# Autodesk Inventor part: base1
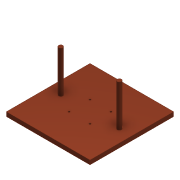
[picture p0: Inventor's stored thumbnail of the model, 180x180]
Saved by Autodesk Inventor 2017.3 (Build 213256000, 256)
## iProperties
Part Number: base1
Material: 銅
Document SubType Name: Modeling
Designer: kyushu-hep
Density: 8.94 g/cm^3
Appearance: 銅 - サテン
Author: kyushu-hep
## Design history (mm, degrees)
sketch "スケッチ3"
  geometry: L1 (-100, 100)-(100, 100); L2 (100, 100)-(100, -100); L3 (100, -100)-(-100, -100); L4 (-100, -100)-(-100, 100); 1 further point
  constraints: 8 end point, 2 parallel, 1 horizontal, 1 perpendicular
  dimensions: "d19" = 100 distance from line of L1 point (0, 0); "d20" = 200 distance of L3.end L1.start; "d21" = 200 distance of L1.start L1.end; "d22" = 100 distance from line of L4 point (0, 0)
extrude "押し出し3" new body sketch "スケッチ3" distance "d23" = 10; taper "d24" = 0 deg
sketch "スケッチ4"
  geometry: C1 r 5 at (-70, 0); C2 r 5 at (70, 0); 1 further point
  constraints: 2 centre point
  dimensions: "d25" = 10 diameter of C1; "d26" = 10 diameter of C2; "d27" = 70 distance of point (0, 0) C1.centre; "d28" = 70 distance of C2.centre point (0, 0)
extrude "押し出し4" join sketch "スケッチ4" distance "d29" = 100; taper "d30" = 0 deg
sketch "スケッチ6"
  geometry: L1 (52, -52)-(-52, -52); L2 (-52, -52)-(-52, 52); L3 (-52, 52)-(52, 52); L4 (52, 52)-(52, -52); L5 (52, -52)-(-52, 52); L6 (-52, -52)-(52, 52); C1 r 2 at (-25, 25); C2 r 2 at (25, 25); C3 r 2 at (-25, -25); C4 r 2 at (25, -25); 1 further point
  constraints: 12 end point, 4 centre point, 2 horizontal, 2 midpoint, 2 parallel, 1 perpendicular, 1 vertical, 6 other
  dimensions: "d38" = 4 diameter of C1; "d40" = 25 horizontal distance of point (0, 0) C1.centre; "d43" = 50 distance of C1.centre C2.centre; "d46" = 50 distance of C1.centre C3.centre; "d51" = 25 horizontal distance of point (0, 0) C2.centre
extrude "押し出し6" cut sketch "スケッチ6" distance "d49" = 10; taper "d50" = 0 deg
node "ソリッド2"
